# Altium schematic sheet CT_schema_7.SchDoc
size 369 x 245 mm
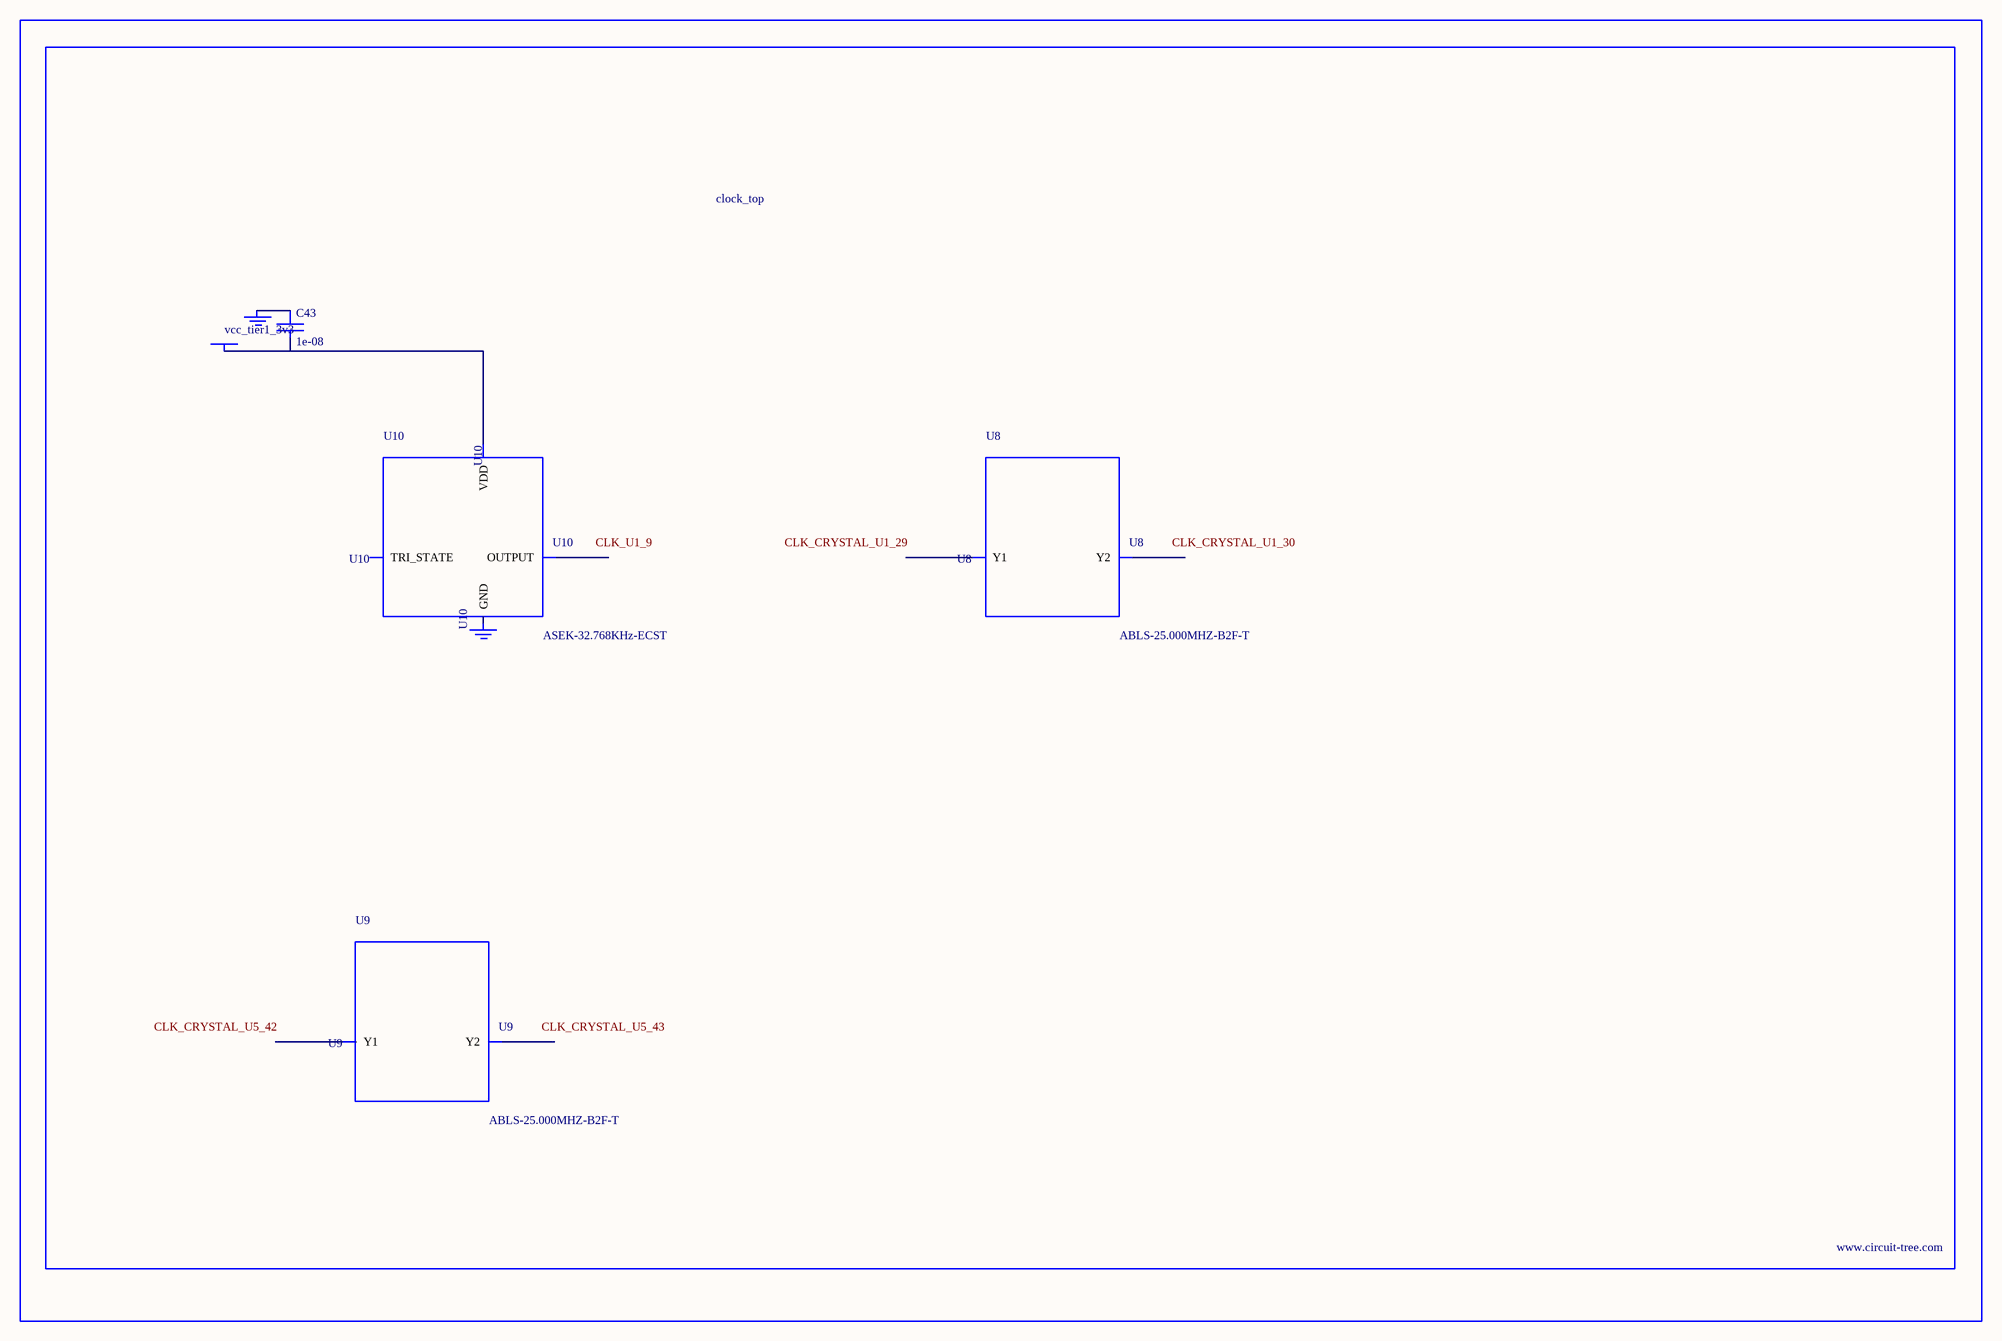
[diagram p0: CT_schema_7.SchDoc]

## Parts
BORDER6  (no value)
C43  1e-08  [C0402]
GND_INSTANCE_6_0  (no value)
GND_INSTANCE_6_1  (no value)
POWER_INSTANCE_6_0  vcc_tier1_3v3
U8  ABLS-25.000MHZ-B2F-T  [ABLS-25.000MHZ-B2F-T]
U9  ABLS-25.000MHZ-B2F-T  [ABLS-25.000MHZ-B2F-T]
U10  ASEK-32.768KHz-ECST  [ASEK]

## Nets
NetC43_1: C43.1 GND_INSTANCE_6_0.0(GND)
NetC43_2: C43.2 POWER_INSTANCE_6_0.0(PWR) U10.4(VDD)

Not connected (* = marked no-connect by the designer): GND_INSTANCE_6_1 0(GND); U8 1(Y1) 2(Y2); U9 1(Y1) 2(Y2); U10 1(TRI_STATE) 2(GND) 3(OUTPUT)

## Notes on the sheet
- Labels drawn without touching a wire or pin: CLK_CRYSTAL_U1_29, CLK_CRYSTAL_U1_30, CLK_CRYSTAL_U5_42, CLK_CRYSTAL_U5_43, CLK_U1_9

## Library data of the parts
BORDER6 = BORDER_PAGE6
C43 = C0402C103K3RAC
GND_INSTANCE_6_0 GND_INSTANCE_6_1 = GND
POWER_INSTANCE_6_0 = PWR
